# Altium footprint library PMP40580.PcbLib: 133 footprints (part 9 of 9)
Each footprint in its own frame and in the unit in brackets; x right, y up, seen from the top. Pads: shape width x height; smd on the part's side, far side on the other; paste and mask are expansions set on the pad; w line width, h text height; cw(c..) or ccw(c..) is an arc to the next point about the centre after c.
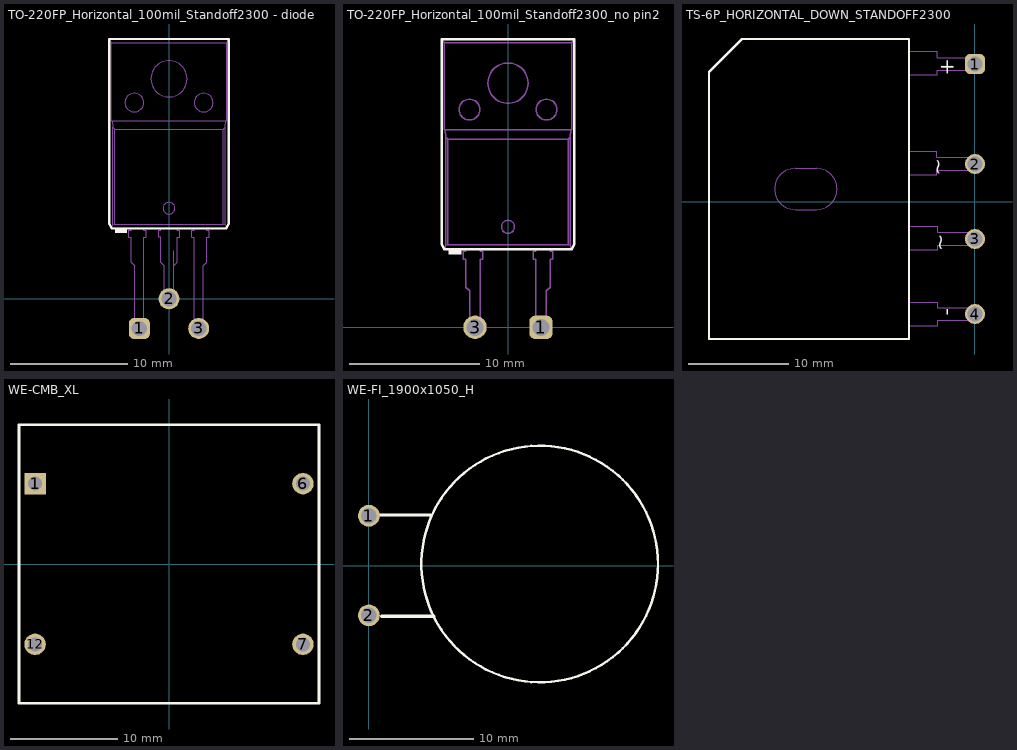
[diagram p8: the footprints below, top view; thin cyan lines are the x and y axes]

## TO-220FP_Horizontal_100mil_Standoff2300 - diode [mm] "TH, 3-Leads, Body 10.4x16mm"
height 6.9
pads (3):
  rrect50% 1.8x1.8 hole 1.3: 1(-2.54,-2.54)
  round 1.8 hole 1.3: 2(0,0) 3(2.54,-2.54)
Top Overlay:
  rectangle: -4.6,5.6 -3.6,6
  lines w0.2: -5.1,6.4 -5.1,22.2 5.1,22.2 5.1,6.4 4.9,6 3.5,6 -4.9,6 -5.1,6.4
Mechanical 5:
  lines w0.1: -2.94,0.755 -2.94,-3.048 -2.14,-3.048 -2.14,0.755 ; 0.4,2.805 0.7,3.105 0.7,5.255 0.9,5.255 0.9,5.855 0.7,5.855 0.7,6.055 -0.7,6.055 -0.7,5.855 -0.897,5.855 -0.897,5.287 -0.7,5.287 -0.7,3.105 -0.4,2.805 -0.4,-0.254 ; 0.4,4.09 0.4,-0.254 ; 2.14,0.755 2.14,-3.048 2.94,-3.048 2.94,0.755 ; -5.09,22.187 -5.09,6.338 -4.917,6.055 -4.883,6.055 ; -5.09,22.187 -4.927,21.905 ; -5.09,22.187 -4.95,22.205 4.95,22.205 5.09,22.187 ; -4.927,21.905 -4.927,15.205 -4.847,15.205 ; -4.927,21.905 4.927,21.905 ; -4.883,6.055 -4.81,6.319 ; -4.883,6.055 4.883,6.055 ; -4.847,15.205 4.847,15.205 ; -4.847,15.205 -4.81,14.647 ; -4.81,6.319 -4.65,6.355 ; -4.81,6.319 -4.81,14.647 ; -4.81,14.647 -4.65,14.498 ; -4.65,6.355 -4.65,14.498 ; -4.65,6.355 4.65,6.355 ; -4.65,14.498 4.65,14.498 ; -0.4,-0.254 0.4,-0.254 ; -0.4,-0.254 -0.4,0.762 0.4,0.762 0.4,-0.254 ; 4.65,6.355 4.65,14.498 ; 4.65,6.355 4.81,6.319 ; 4.65,14.498 4.81,14.647 ; 4.81,6.319 4.81,14.647 ; 4.81,6.319 4.883,6.055 ; 4.81,14.647 4.847,15.205 ; 4.847,15.205 4.927,15.205 4.927,21.905 ; 4.883,6.055 4.917,6.055 5.09,6.338 5.09,22.187 ; 4.927,21.905 5.09,22.187 ; -3.768,16.767 ccw(c-2.968,16.767) -2.168,16.767 ccw(c-2.968,16.767) -3.768,16.767 ; -3.44,5.255 -3.24,5.255 -3.24,3.105 -2.94,2.805 -2.94,-2.032 -2.14,-2.032 -2.14,5.255 -1.94,5.255 -1.94,5.855 -2.14,5.855 -2.14,6.055 -3.24,6.055 -3.24,5.855 -3.44,5.855 -3.44,5.255 ; -1.55,18.805 ccw(c0,18.805) 1.55,18.805 ccw(c0,18.805) -1.55,18.805 ; -0.5,7.741 cw(c0,7.741) 0.5,7.741 cw(c0,7.741) -0.5,7.741 ; 1.94,5.255 2.14,5.255 2.14,-2.032 2.94,-2.032 2.94,2.805 3.24,3.105 3.24,5.255 3.44,5.255 3.44,5.855 3.24,5.855 3.24,6.055 2.14,6.055 2.14,5.855 1.94,5.855 1.94,5.255 ; 2.168,16.767 ccw(c2.968,16.767) 3.768,16.767 ccw(c2.968,16.767) 2.168,16.767
  text ".Designator" at -3.1,8.8 h1.85

## TO-220FP_Horizontal_100mil_Standoff2300_no pin2 [mm] "TH, 3-Leads, Body 10.4x16mm"
height 6.9
pads (2):
  rrect50% 1.8x1.8 hole 1.3: 1(2.54,0)
  round 1.8 hole 1.3: 3(-2.54,0)
Top Overlay:
  rectangle: -4.6,5.6 -3.6,6
  lines w0.2: -5.1,6.4 -4.9,6 3.5,6 4.9,6 5.1,6.4 5.1,22.2 -5.1,22.2 -5.1,6.4
Mechanical 5:
  lines w0.1: -5.09,22.187 -4.95,22.205 4.95,22.205 5.09,22.187 ; -5.09,22.187 -4.927,21.905 ; -5.09,22.187 -5.09,6.338 -4.917,6.055 -4.883,6.055 ; -4.927,21.905 4.927,21.905 ; -4.927,21.905 -4.927,15.205 -4.847,15.205 ; -4.883,6.055 4.883,6.055 ; -4.883,6.055 -4.81,6.319 ; -4.847,15.205 -4.81,14.647 ; -4.847,15.205 4.847,15.205 ; -4.81,6.319 -4.81,14.647 ; -4.81,6.319 -4.65,6.355 ; -4.81,14.647 -4.65,14.498 ; -4.65,6.355 4.65,6.355 ; -4.65,6.355 -4.65,14.498 ; -4.65,14.498 4.65,14.498 ; -2.94,0.755 -2.94,-0.245 -2.14,-0.245 -2.14,0.755 ; -2.94,0.755 -2.94,2.805 -3.24,3.105 -3.24,5.255 -3.44,5.255 -3.44,5.855 -3.24,5.855 -3.24,6.055 -2.14,6.055 -2.14,5.855 -1.94,5.855 -1.94,5.255 -2.14,5.255 -2.14,0.755 ; -2.94,0.755 -2.14,0.755 ; 2.14,0.755 2.14,-0.245 2.94,-0.245 2.94,0.755 ; 2.14,0.755 2.14,5.255 1.94,5.255 1.94,5.855 2.14,5.855 2.14,6.055 3.24,6.055 3.24,5.855 3.44,5.855 3.44,5.255 3.24,5.255 3.24,3.105 2.94,2.805 2.94,0.755 ; 2.14,0.755 2.94,0.755 ; 4.65,6.355 4.81,6.319 ; 4.65,6.355 4.65,14.498 ; 4.65,14.498 4.81,14.647 ; 4.81,6.319 4.883,6.055 ; 4.81,6.319 4.81,14.647 ; 4.81,14.647 4.847,15.205 ; 4.847,15.205 4.927,15.205 4.927,21.905 ; 4.883,6.055 4.917,6.055 5.09,6.338 5.09,22.187 ; 4.927,21.905 5.09,22.187 ; -3.768,16.767 cw(c-2.968,16.767) -2.168,16.767 cw(c-2.968,16.767) -3.768,16.767 ; -1.55,18.805 cw(c0,18.805) 1.55,18.805 cw(c0,18.805) -1.55,18.805 ; -0.5,7.741 ccw(c0,7.741) 0.5,7.741 ccw(c0,7.741) -0.5,7.741 ; 2.168,16.767 cw(c2.968,16.767) 3.768,16.767 cw(c2.968,16.767) 2.168,16.767
  text ".Designator" at -3.1,8.8 h1.85

## TS-6P_HORIZONTAL_DOWN_STANDOFF2300 [mm] "TH, 4-Leads, Body 22.3x18.8mm, Pitch 5.08"
height 5.86
pads (4):
  rrect50% 2x2 hole 1.5: 1(0,13.75)
  round 2 hole 1.5: 2(0,3.75) 3(0,-3.75) 4(0,-11.25)
Top Overlay:
  lines w0.2: -26.6,-13.75 -6.6,-13.75 -6.6,16.25 -23.3,16.25 -26.6,12.95 -26.6,-13.75
  text "~" at -4.075,-3.225 h1.52
  text "~" at -4.325,4.325 h1.52
  text "-" at -3.325,-10.7 h1.52
  text "+" at -3.35,14.35 h1.52
Mechanical 5:
  lines w0.1: -17,3.3 -16.9,3.3 ; -6.6,2.7 -3.85,2.7 -3.85,3.144 -0.82,3.144 0.18,3.144 0.18,4.414 -0.82,4.414 -3.85,4.414 -3.85,5.05 -6.6,5.05 ; -6.5,-4.8 -3.75,-4.8 -3.75,-4.356 -0.72,-4.356 0.28,-4.356 0.28,-3.086 -0.72,-3.086 -3.75,-3.086 -3.75,-2.45 -6.5,-2.45 ; -6.5,12.675 -3.75,12.675 -3.75,13.119 -0.72,13.119 0.28,13.119 0.28,14.389 -0.72,14.389 -3.75,14.389 -3.75,15.025 -6.5,15.025 ; -6.48,-12.415 -3.73,-12.415 -3.73,-11.875 -0.7,-11.875 0.3,-11.875 0.3,-10.605 -0.7,-10.605 -3.73,-10.605 -3.73,-10.065 -6.48,-10.065 ; -26.6,-13.75 -6.6,-13.75 -6.6,16.25 -23.3,16.25 -26.6,12.95 -26.6,-13.75 ; -18,-0.8 cw(c-18,1.25) -18,3.3 -15.84,3.3 cw(c-15.84,1.25) -15.84,-0.8 -18,-0.8
  text ".Designator" at -8.64,-8.25 h1.85

## WE-CMB_XL [mm] "Wurth"
height 35
pads (4):
  rect 2x2 hole 1.3: 1(-12.5,7.5)
  round 2 hole 1.3: 6(12.5,7.5) 7(12.5,-7.5) 12(-12.5,-7.5)
Top Overlay:
  lines w0.254: -14,-13 -14,13 14,13 14,-13 -14,-13

## WE-FI_1900x1050_H [mm] "TH, 2-Leads, Dia 19mm, Pin Spacing 8mm"
height 19
pads (2):
  round 1.75 hole 1.25: 1(0,4) 2(0,-4)
Top Overlay:
  circle w0.2: c13.716,0.127 r9.5
  lines w0.254: 0.444,4.064 4.953,4.064 ; 1.016,-4.064 5.207,-4.064
Mechanical 5:
  text ".Designator" at -2,-0.7 h1.85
